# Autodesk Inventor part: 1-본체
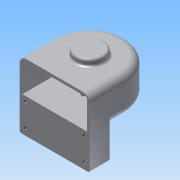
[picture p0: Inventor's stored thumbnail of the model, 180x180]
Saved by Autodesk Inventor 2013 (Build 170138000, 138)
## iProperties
Created: 2015-02
Part Number: 1-본체
Material: 알루미늄 6061
Document SubType Name: Modeling
Designer: Administrator
Density: 2.71 g/cm^3
Mass: 565.472 g
Surface Area: 719.016 cm^2
Volume: 208.661 cm^3
Author: Administrator
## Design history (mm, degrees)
sketch "스케치1"
  geometry: L1 (-50, 0)-(-50, -50); L2 (50, -50)-(50, 0); L3 (-50, -50)-(50, -50); L4 (-34.641, -20)-(-50, -20); L5 (34.641, -20)-(50, -20); L6 (-34.641, -20)-(-34.641, -50); L7 (34.641, -20)-(34.641, -50); A1 r 50 centre (0, 0) between (-50, 0) and (50, 0); A2 r 40 centre (0, 0) between (-34.641, -20) and (34.641, -20); 1 further point
  constraints: 14 end point, 5 perpendicular, 4 point on circle, 4 point on line, 3 tangent, 2 centre point, 2 coincident, 1 collinear, 1 parallel, 1 vertical
  dimensions: "d0" = 50 radius of A1; "d3" = 40 radius of A2; "d4" = 30 distance between parallel lines of L3 L4
extrude "돌출1" new body sketch "스케치1" distance "d5" = 50; taper "d6" = 0 deg
feature "쉘1" dims "d9" = 4
extrude "돌출2" join sketch "스케치1" distance "d7" = 45; taper "d8" = 0 deg
sketch "스케치2"
  geometry: C1 r 25 at (0, 0); A1 r 50 centre (0, 0) between (50, 0) and (-50, 0) reference; A2 r 40 centre (0, 0) between (-34.641, -20) and (34.641, -20) reference
  constraints: 2 coincident, 1 centre point
  dimensions: "d10" = 50 diameter of C1
extrude "돌출3" join sketch "스케치2" distance "d12" = 10; taper "d13" = -20 deg
sketch "스케치3"
  geometry: C1 r 20 at (0, 0); A1 r 50 centre (0, 0) between (50, 0) and (-50, 0) reference
  constraints: 1 centre point, 1 coincident
  dimensions: "d14" = 40 diameter of C1
extrude "돌출4" join sketch "스케치3" distance "d16" = 9; taper "d17" = 0 deg
hole "구멍1" diameter "d20" = 20; stored, may be unused: countersink angle "d24" = 90 deg, drill point angle "d26" = 0 deg; dims "d18" = 10, "d19" = 10, "d21" = 6, "d22" = 28, "d23" = 10, "d25" = 14
hole "구멍2" diameter "d29" = 20; stored, may be unused: countersink angle "d33" = 90 deg, drill point angle "d35" = 0 deg; dims "d27" = 10, "d28" = 10, "d30" = 6, "d31" = 28, "d32" = 8, "d34" = 10
sketch "스케치4"
  geometry: C1 r 14 at (0, 0) reference; C2 r 21.36 at (0, 0) reference; A1 r 18 centre (0, 0) between (0, 18) and (18, 0); 2 further points
  constraints: 4 point on circle, 2 horizontal alignment, 2 vertical alignment, 1 centre point, 1 coincident
  dimensions: "d36" = 36 diameter of A1
hole "구멍3" sketch "스케치4" at (0, 18), (18, 0), (0, -18), (-18, 0) diameter "d38" = 2.459; stored, may be unused: countersink angle "d42" = 90 deg, drill point angle "d44" = 118 deg; dims "d39" = 6, "d40" = 28, "d41" = 8, "d43" = 9
fillet "모깎기2" dims "d46" = 10
fillet "모깎기3" dims "d47" = 3
fillet "모깎기4" dims "d48" = 3
fillet "모깎기5" dims "d49" = 3
chamfer "모따기1" distance "d50" = 1; stored, may be unused: second distance "d51" = 2, angle "d52" = 45 deg
fillet "모깎기6" dims "d53" = 0.3
sketch "스케치5"
  geometry: L1 (87, -95)-(-7, -95) reference; 6 further points
  constraints: 2 horizontal alignment, 2 vertical alignment, 1 midpoint
  dimensions: "d54" = 9 distance from line of L1 point (-1.75, -86); "d55" = 33 distance of point (-1.75, -86) point (-1.75, -53); "d56" = 83.5 distance of point (81.75, -86) point (-1.75, -86); "d57" = 41.75 horizontal distance of point (-1.75, -86) point (40, -95)
hole "구멍4" sketch "스케치5" at (-1.75, -53), (-1.75, -86), (81.75, -53), (81.75, -86) diameter "d58" = 5.134; stored, may be unused: countersink angle "d62" = 90 deg, drill point angle "d64" = 118 deg; dims "d59" = 10, "d60" = 28, "d61" = 8, "d63" = 13
node "작업 평면1"
sketch "스케치6"
  geometry: L1 (-40, 50)-(40, 50) reference; 3 further points
  constraints: 1 midpoint, 1 vertical alignment, 1 other
  dimensions: "d66" = 25 distance from line of point (0, 25) L1
feature "엠보싱1" sketch "스케치6" dims "d0" = 50, "d3" = 40, "d4" = 30, "d67" = 0.5, "d68" = 0
node "솔리드1"
other parameters: "d65" = 88
